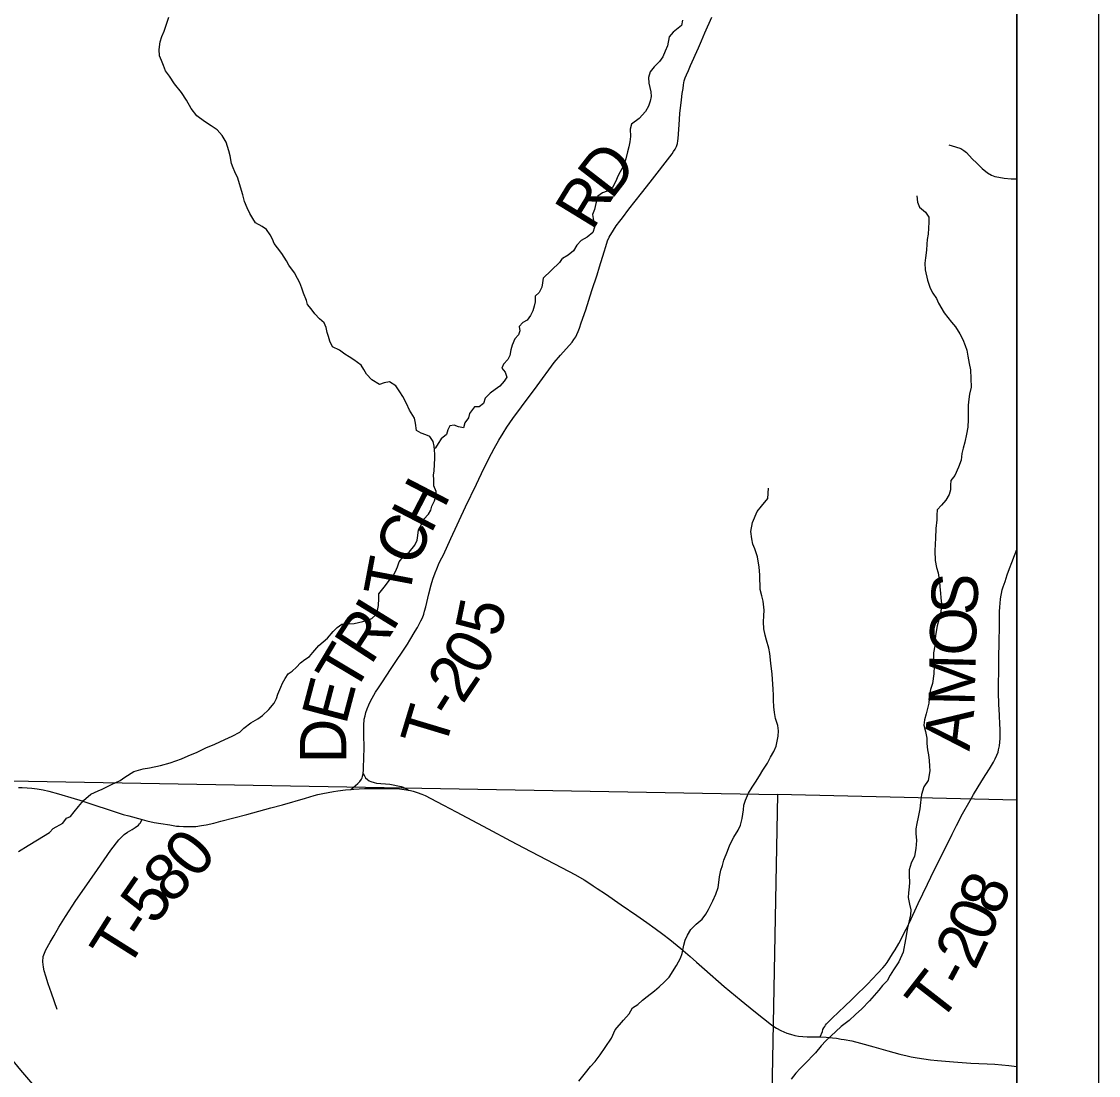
# Model space of a CAD drawing. Extents: x 0 to 34, y 0 to 22.
# Drawn here: x 7.678 to 9, y 16.54 to 17.833 of the extents above; entities that cross this region are included whole.
import ezdxf

# ---------------------------------------------------------------- set-up
doc = ezdxf.new("R2010")
doc.units = 0
for name, color, linetype in [('GM_X_County_Road', 7, 'Continuous'), ('GM_X_Interchange_Ramps', 7, 'Continuous'), ('GM_X_Interstate_Route', 7, 'Continuous'), ('GM_X_Minor_Lake', 7, 'Continuous'), ('GM_X_Section', 7, 'Continuous'), ('GM_X_Township_Road_Text', 7, 'Continuous'), ('GM_X_Unincorporated_Text', 7, 'Continuous'), ('SH_Cut_Line', 7, 'Continuous'), ('SH_Data', 7, 'Continuous')]:
    doc.layers.add(name, color=color, linetype=linetype)

msp = doc.modelspace()

# ---------------------------------------------------------------- linework, layer by layer
at = {"layer": 'GM_X_County_Road'}
msp.add_lwpolyline([(8.9, 16.3458), (8.8896, 16.3484), (8.8415, 16.3566), (8.7835, 16.3626), (8.6949, 16.3631), (8.0785, 16.3449), (8.0171, 16.3505), (7.9686, 16.3596), (7.9232, 16.3737), (7.8664, 16.3974), (7.8219, 16.4192), (7.7822, 16.4429), (7.7542, 16.4676), (7.7187, 16.4982), (7.6774, 16.5465), (7.4755, 16.7917), (7.4147, 16.863), (7.366, 16.9092), (7.315, 16.9447), (7.2325, 16.9942), (7.0394, 17.1127), (6.8369, 17.2379), (6.5407, 17.4237)], dxfattribs=at)
at = {"layer": 'GM_X_Interchange_Ramps'}
msp.add_lwpolyline([(6.5113, 14.1), (8.9, 14.1), (8.9, 17.8921), (8.5492, 17.9006), (8.3297, 17.9059), (7.6027, 17.9156), (6.5943, 17.9356), (6.5883, 17.471), (6.5647, 16.5359), (6.5572, 16.1864), (6.5411, 15.4243), (6.5389, 15.3228)], close=True, dxfattribs=at)
for points in [[(7.6744, 16.8931), (7.6789, 16.8932), (7.6851, 16.893), (7.6909, 16.8924), (7.6973, 16.8916), (7.7048, 16.8902), (7.7118, 16.8886), (7.7235, 16.8855), (7.7428, 16.8798), (7.7498, 16.8776), (7.8031, 16.8603), (7.81, 16.8583), (7.8264, 16.8538), (7.8321, 16.8525), (7.841, 16.8504), (7.8492, 16.8489), (7.8601, 16.8473), (7.8684, 16.846), (7.8716, 16.8457), (7.8772, 16.8455), (7.8847, 16.8454), (7.8921, 16.8456), (7.8991, 16.8465), (7.9049, 16.8474), (7.9141, 16.8495), (7.9229, 16.8518), (7.9546, 16.86), (7.9841, 16.8683), (7.9987, 16.8721), (8.0268, 16.8802), (8.0373, 16.8833), (8.0421, 16.8845), (8.0479, 16.8859), (8.0613, 16.8885), (8.0666, 16.8893), (8.0757, 16.8903), (8.0825, 16.8909), (8.0862, 16.8913), (8.0992, 16.8919), (8.1214, 16.8922), (8.1349, 16.892), (8.1421, 16.8916), (8.1478, 16.8909), (8.1531, 16.8901)], [(8.1531, 16.8901), (8.1555, 16.8897), (8.1591, 16.8888), (8.1639, 16.8873), (8.1695, 16.8852), (8.1737, 16.8833), (8.1877, 16.8762), (8.1963, 16.8717), (8.2118, 16.8636), (8.2511, 16.8425), (8.2784, 16.8279), (8.2949, 16.8194), (8.3409, 16.7951), (8.3581, 16.786), (8.3686, 16.7799), (8.3759, 16.7753), (8.3798, 16.7728), (8.3849, 16.7694), (8.3951, 16.7627), (8.4142, 16.7495), (8.4333, 16.7363), (8.4457, 16.7275), (8.456, 16.7202), (8.4655, 16.7132), (8.4739, 16.7067), (8.4875, 16.6956), (8.4989, 16.6858), (8.5066, 16.6788), (8.5163, 16.6703), (8.5406, 16.6493), (8.5616, 16.632), (8.5771, 16.6191), (8.5888, 16.6097), (8.5945, 16.6053), (8.5993, 16.6017), (8.605, 16.5981), (8.6102, 16.5951), (8.6138, 16.5934), (8.6177, 16.5919), (8.6222, 16.5905), (8.6273, 16.5892), (8.6318, 16.5884), (8.6372, 16.5878), (8.6425, 16.5875), (8.6486, 16.5873), (8.6583, 16.5874)], [(8.6583, 16.5874), (8.666, 16.5871), (8.6734, 16.5863), (8.6784, 16.5857), (8.6843, 16.5847), (8.6877, 16.584), (8.6971, 16.5823), (8.7078, 16.5796), (8.7244, 16.5752), (8.733, 16.5727), (8.7415, 16.5704), (8.7562, 16.5662), (8.7651, 16.5641), (8.7702, 16.563), (8.7775, 16.5617), (8.7855, 16.5604), (8.794, 16.5593), (8.8024, 16.5582), (8.8121, 16.5574), (8.8222, 16.5566), (8.8433, 16.5552), (8.8532, 16.5546), (8.8636, 16.5544), (8.8727, 16.554), (8.8814, 16.5532), (8.8901, 16.5524), (8.9, 16.551)]]:
    msp.add_lwpolyline(points, dxfattribs=at)
at = {"layer": 'GM_X_Interstate_Route'}
for points in [[(8.0825, 16.8909), (8.0854, 16.8932), (8.0883, 16.8957), (8.091, 16.8982), (8.0933, 16.9005), (8.0955, 16.9033), (8.0963, 16.9051), (8.0969, 16.9069), (8.0977, 16.9103), (8.0979, 16.9148), (8.0981, 16.9178), (8.0985, 16.9292), (8.0988, 16.9423), (8.0984, 16.958), (8.0983, 16.9669), (8.0985, 16.9717), (8.0986, 16.9745), (8.0989, 16.9769), (8.0998, 16.981), (8.1009, 16.9852), (8.1026, 16.9896), (8.1044, 16.9946), (8.1064, 16.999), (8.1127, 17.0101), (8.1163, 17.0157), (8.1203, 17.0218), (8.1318, 17.0391), (8.1518, 17.0692), (8.1547, 17.0738), (8.1613, 17.0849), (8.1642, 17.0895), (8.1684, 17.0978), (8.1702, 17.1012), (8.1719, 17.1059), (8.173, 17.1096), (8.1745, 17.115), (8.1782, 17.1306), (8.1811, 17.1417), (8.1831, 17.1487), (8.1859, 17.1564), (8.1879, 17.1614), (8.191, 17.1687), (8.1941, 17.175), (8.196, 17.1788), (8.2053, 17.1987), (8.2233, 17.2376), (8.2365, 17.2654), (8.2458, 17.2847), (8.255, 17.3029), (8.2582, 17.3089), (8.264, 17.3193), (8.2692, 17.3279), (8.2738, 17.3351), (8.2814, 17.3457), (8.2917, 17.36), (8.3109, 17.3859), (8.3321, 17.4146), (8.3399, 17.4237), (8.3542, 17.4396), (8.3563, 17.4427), (8.3584, 17.4462), (8.3599, 17.4491), (8.3614, 17.4527), (8.363, 17.4566), (8.3652, 17.4633), (8.3707, 17.4791), (8.3782, 17.5027), (8.3846, 17.5222), (8.3878, 17.5318), (8.3935, 17.5504), (8.3954, 17.557), (8.3974, 17.5637), (8.3994, 17.5681), (8.4047, 17.577), (8.4082, 17.5821), (8.4127, 17.5881), (8.4158, 17.592), (8.4238, 17.6026), (8.4392, 17.6222), (8.4496, 17.6358), (8.4766, 17.6704), (8.4786, 17.6733), (8.4805, 17.6764), (8.4822, 17.6797), (8.4832, 17.6832), (8.4837, 17.6863), (8.4841, 17.6893), (8.4853, 17.7059), (8.4864, 17.7198), (8.4883, 17.7368), (8.489, 17.7446), (8.4901, 17.7507), (8.4907, 17.7551), (8.4916, 17.76), (8.4929, 17.7636), (8.4945, 17.7673), (8.4968, 17.7729), (8.4993, 17.7788), (8.5093, 17.8007), (8.5128, 17.809), (8.517, 17.8189), (8.5254, 17.8382)], [(8.8163, 17.6816), (8.8247, 17.6792), (8.8309, 17.6771), (8.8349, 17.6747), (8.838, 17.672), (8.8448, 17.6643), (8.8507, 17.6589), (8.8573, 17.6527), (8.8637, 17.6473), (8.8687, 17.6445), (8.8727, 17.6429), (8.8776, 17.6417), (8.8841, 17.6407), (8.893, 17.64), (8.9, 17.64)], [(8.6583, 16.5874), (8.6611, 16.5941), (8.6619, 16.5962), (8.6629, 16.5983), (8.664, 16.6001), (8.6649, 16.6016), (8.6663, 16.6034), (8.6689, 16.6061), (8.6732, 16.6103), (8.6887, 16.6249), (8.6969, 16.6328), (8.7007, 16.6364), (8.7165, 16.6519), (8.7289, 16.6651), (8.7353, 16.672), (8.7384, 16.6754), (8.7407, 16.6787), (8.7441, 16.6838), (8.7474, 16.6893), (8.7504, 16.6943), (8.7548, 16.7019), (8.7639, 16.7196), (8.7679, 16.7277), (8.7789, 16.7508), (8.7901, 16.7745), (8.7944, 16.7831), (8.803, 16.8009), (8.8068, 16.8087), (8.8203, 16.8359), (8.8256, 16.8466), (8.8333, 16.8608), (8.8425, 16.8772), (8.8468, 16.8846), (8.8568, 16.9013), (8.8616, 16.909), (8.8663, 16.9163), (8.8711, 16.9242), (8.8734, 16.9285), (8.8754, 16.9329), (8.8767, 16.9364), (8.8775, 16.9393), (8.8784, 16.9443), (8.8789, 16.949), (8.8792, 16.9533), (8.8794, 16.9657), (8.8791, 16.9701), (8.8784, 16.9822), (8.8779, 16.9949), (8.8774, 17.01), (8.8773, 17.0175), (8.8776, 17.0389), (8.8778, 17.051), (8.8781, 17.0727), (8.8784, 17.09), (8.8787, 17.109), (8.879, 17.1145), (8.8798, 17.1241), (8.8801, 17.127), (8.8809, 17.1313), (8.882, 17.1356), (8.8832, 17.1394), (8.8853, 17.1458), (8.888, 17.154), (8.8908, 17.1618), (8.8936, 17.1693), (8.897, 17.1777), (8.9, 17.185)], [(8.0977, 16.9103), (8.099, 16.9076), (8.1004, 16.9053), (8.1027, 16.9031), (8.105, 16.9016), (8.1069, 16.9006), (8.1111, 16.8993), (8.1139, 16.8986), (8.1302, 16.8973), (8.1324, 16.8969), (8.142, 16.895), (8.1442, 16.8943), (8.1466, 16.8935), (8.1494, 16.8922), (8.151, 16.8914), (8.1531, 16.8901)], [(7.7221, 16.6209), (7.7149, 16.6408), (7.7109, 16.6524), (7.7079, 16.6619), (7.7062, 16.6682), (7.705, 16.6727), (7.7046, 16.676), (7.7043, 16.6796), (7.7049, 16.6858), (7.7064, 16.69), (7.7082, 16.6943), (7.7134, 16.7037), (7.7182, 16.7119), (7.7241, 16.7221), (7.7323, 16.7349), (7.7449, 16.7545), (7.7525, 16.7657), (7.7619, 16.7792), (7.7716, 16.7925), (7.7877, 16.8163), (7.7977, 16.8292), (7.8012, 16.8328), (7.8044, 16.8357), (7.8085, 16.8385), (7.8139, 16.8417), (7.8179, 16.8441), (7.8217, 16.8471), (7.8231, 16.8486), (7.8239, 16.8496), (7.8264, 16.8538)]]:
    msp.add_lwpolyline(points, dxfattribs=at)
at = {"layer": 'GM_X_Minor_Lake'}
msp.add_lwpolyline([(7.5942, 16.9027), (8.606, 16.8847), (8.5869, 15.8686), (7.5725, 15.8874)], close=True, dxfattribs=at)
at = {"layer": 'GM_X_Township_Road_Text'}
for points in [[(7.9788, 17.5777), (7.9735, 17.5814), (7.9654, 17.5859), (7.962, 17.5912), (7.9585, 17.5972), (7.9553, 17.6044), (7.9518, 17.612), (7.9498, 17.6203), (7.947, 17.6298), (7.9438, 17.6408), (7.94, 17.6483), (7.938, 17.6533), (7.936, 17.6586), (7.9344, 17.6681), (7.9328, 17.6741), (7.9292, 17.6848), (7.9246, 17.6931), (7.9184, 17.6998), (7.9108, 17.7047), (7.9027, 17.7102), (7.8935, 17.7173), (7.8866, 17.726), (7.8808, 17.7362), (7.8746, 17.7456), (7.8661, 17.7565), (7.8599, 17.7656), (7.8549, 17.7724), (7.8525, 17.7788), (7.8502, 17.7849), (7.8475, 17.7909), (7.847, 17.7985), (7.8484, 17.8077), (7.8505, 17.8146), (7.8535, 17.8211), (7.8564, 17.8307), (7.8589, 17.838)], [(8.4896, 17.8345), (8.4881, 17.828), (8.4782, 17.8197), (8.4732, 17.814), (8.4709, 17.803), (8.4682, 17.7965), (8.4655, 17.7897), (8.4613, 17.7836), (8.4545, 17.7772), (8.4499, 17.7711), (8.4476, 17.7642), (8.4483, 17.7574), (8.4505, 17.7467), (8.4509, 17.7407), (8.4497, 17.735), (8.4478, 17.7289), (8.4439, 17.7224), (8.4363, 17.7137), (8.4268, 17.7069), (8.4253, 17.7008), (8.4256, 17.6917), (8.4248, 17.6852), (8.4236, 17.6791), (8.4221, 17.6731), (8.4198, 17.6643), (8.4175, 17.6567), (8.4106, 17.6438), (8.4071, 17.6362), (8.4037, 17.6294), (8.3972, 17.6249), (8.3911, 17.6226), (8.3854, 17.6184), (8.3831, 17.6097), (8.3815, 17.6021), (8.3792, 17.596), (8.3807, 17.5861), (8.3814, 17.5804), (8.3795, 17.574), (8.3723, 17.5683), (8.365, 17.5641), (8.3597, 17.5584), (8.3555, 17.5516), (8.349, 17.5463), (8.3422, 17.5421), (8.342, 17.5419)], [(8.777, 17.6189), (8.7781, 17.6113), (8.7803, 17.6052), (8.7879, 17.5991), (8.792, 17.593), (8.792, 17.5865), (8.7908, 17.5721), (8.7896, 17.5656), (8.7892, 17.5599), (8.7888, 17.5523), (8.7876, 17.5428), (8.7868, 17.5364), (8.7872, 17.5284), (8.7902, 17.5154), (8.7935, 17.5059), (8.7969, 17.4998), (8.8011, 17.493), (8.8037, 17.4872), (8.8108, 17.4754), (8.8195, 17.464), (8.8244, 17.4583), (8.8297, 17.4499), (8.8335, 17.4427), (8.8365, 17.4354), (8.8383, 17.4297), (8.8398, 17.4225), (8.8413, 17.4133), (8.8428, 17.4057), (8.8435, 17.3951), (8.8438, 17.3844), (8.8419, 17.3757), (8.8407, 17.3696), (8.8399, 17.3624), (8.8399, 17.3533), (8.8402, 17.3445), (8.8398, 17.3354), (8.8382, 17.3267), (8.8359, 17.3168), (8.834, 17.3096), (8.8324, 17.3031), (8.8313, 17.2948), (8.8282, 17.286), (8.8236, 17.2758), (8.819, 17.2697), (8.8186, 17.264), (8.8186, 17.2583), (8.8167, 17.2526), (8.8125, 17.2458), (8.8075, 17.2397), (8.8022, 17.234), (8.8017, 17.2272), (8.8017, 17.2215), (8.8005, 17.2109), (8.8001, 17.1991), (8.7997, 17.1919), (8.7993, 17.1835), (8.7996, 17.1717), (8.8011, 17.1633), (8.8033, 17.1565), (8.8048, 17.1455), (8.8055, 17.1394), (8.8062, 17.1318), (8.8066, 17.1257), (8.8073, 17.1185), (8.8065, 17.1082), (8.8042, 17.0991), (8.8019, 17.0915), (8.8003, 17.082), (8.7995, 17.0759), (8.7991, 17.0672), (8.7976, 17.0584), (8.7975, 17.0527), (8.7983, 17.0425), (8.7978, 17.0326), (8.7963, 17.0208), (8.794, 17.0136), (8.7928, 17.0068), (8.792, 16.9965), (8.7885, 16.9836), (8.7866, 16.9764), (8.7858, 16.9699), (8.7877, 16.9619), (8.7895, 16.9536), (8.7895, 16.9471), (8.7902, 16.9395), (8.7913, 16.9334), (8.7924, 16.9262), (8.7928, 16.9193), (8.7931, 16.9136), (8.7908, 16.9019), (8.7855, 16.8939), (8.7828, 16.8848), (8.7816, 16.8749), (8.7808, 16.8669), (8.7788, 16.857), (8.7769, 16.8491), (8.7757, 16.8426), (8.7757, 16.8369), (8.7768, 16.8282), (8.776, 16.8183), (8.7741, 16.8092)], [(7.9912, 17.0025), (7.993, 17.0079), (7.9963, 17.0163), (7.9985, 17.0213), (8.0018, 17.0271), (8.0055, 17.0328), (8.0104, 17.0359), (8.0156, 17.041), (8.0205, 17.046), (8.0261, 17.0503), (8.0317, 17.0538), (8.0358, 17.0588), (8.0433, 17.0673), (8.0538, 17.0766), (8.0608, 17.0847), (8.0657, 17.0897), (8.0713, 17.0936), (8.0766, 17.0941), (8.0864, 17.0946), (8.097, 17.0967), (8.103, 17.0983), (8.1083, 17.1006), (8.1135, 17.1053), (8.115, 17.1103), (8.1164, 17.1164), (8.1167, 17.1251), (8.1166, 17.1308), (8.1248, 17.1409), (8.1296, 17.147), (8.1344, 17.1528), (8.1374, 17.1582), (8.1396, 17.1639), (8.1418, 17.1701), (8.1462, 17.1758), (8.1541, 17.1821), (8.1608, 17.1905), (8.1637, 17.1967), (8.1648, 17.2024), (8.1654, 17.2093), (8.1695, 17.2166), (8.1721, 17.2223), (8.1776, 17.2285), (8.1806, 17.2335), (8.182, 17.2385), (8.185, 17.245), (8.1868, 17.2507), (8.1871, 17.2564), (8.1843, 17.2632), (8.1842, 17.2712), (8.1838, 17.2762), (8.1845, 17.2815), (8.1854, 17.2971), (8.1853, 17.3021), (8.1848, 17.312), (8.1836, 17.3177), (8.1793, 17.3237), (8.1744, 17.3259), (8.1687, 17.3277), (8.1629, 17.3311), (8.1617, 17.3402), (8.1604, 17.3463), (8.1546, 17.3561), (8.1507, 17.3644), (8.1461, 17.3727), (8.1426, 17.3784), (8.1375, 17.3859), (8.1299, 17.3907), (8.1235, 17.3895), (8.1174, 17.3875), (8.1083, 17.3935), (8.1017, 17.4002), (8.0983, 17.4059), (8.0951, 17.4112), (8.086, 17.4179), (8.0802, 17.4216), (8.0749, 17.4246), (8.0684, 17.4298), (8.06, 17.4338), (8.0565, 17.4406), (8.0549, 17.4463), (8.0533, 17.4513), (8.0521, 17.4573), (8.0497, 17.4634), (8.044, 17.4683), (8.0382, 17.4743), (8.0336, 17.4803), (8.0293, 17.4856), (8.0278, 17.4905), (8.0242, 17.4996), (8.0222, 17.5056), (8.0199, 17.5121), (8.0168, 17.5177), (8.0133, 17.5245), (8.0063, 17.534), (8.0036, 17.5392), (7.9978, 17.5483), (7.9924, 17.5554), (7.9885, 17.5607), (7.9862, 17.566), (7.9834, 17.5713), (7.9788, 17.5777)], [(8.3418, 17.542), (8.3385, 17.5373), (8.3185, 17.5182), (8.3175, 17.5124), (8.3168, 17.5071), (8.3135, 17.5006), (8.3086, 17.4959), (8.3087, 17.4891), (8.3073, 17.4837), (8.3058, 17.478), (8.3029, 17.4722), (8.2988, 17.4664), (8.2936, 17.4637), (8.2891, 17.4587), (8.2899, 17.4534), (8.2881, 17.4484), (8.2836, 17.4434), (8.2803, 17.4357), (8.2789, 17.43), (8.2775, 17.4231), (8.2753, 17.4181), (8.2697, 17.4127), (8.2678, 17.4077), (8.2717, 17.4028), (8.2737, 17.3967), (8.2707, 17.3917), (8.2651, 17.3856), (8.2595, 17.3813), (8.2535, 17.377), (8.2472, 17.3708), (8.2454, 17.3643), (8.2398, 17.36), (8.2341, 17.36), (8.2281, 17.3519), (8.2267, 17.3465), (8.2222, 17.3404), (8.2208, 17.3346), (8.2144, 17.3357), (8.2094, 17.3375), (8.2041, 17.337), (8.2015, 17.332), (8.1997, 17.3263), (8.1934, 17.3209), (8.1897, 17.3151), (8.1863, 17.3097), (8.185, 17.3087)], [(8.3623, 16.5332), (8.3703, 16.5434), (8.3764, 16.551), (8.3821, 16.5571), (8.3883, 16.5654), (8.3944, 16.5745), (8.4024, 16.5859), (8.407, 16.5958), (8.4169, 16.6079), (8.4241, 16.6158), (8.428, 16.623), (8.4348, 16.6272), (8.4405, 16.6325), (8.4462, 16.637), (8.455, 16.6438), (8.4607, 16.6488), (8.4672, 16.6548), (8.4733, 16.6605), (8.4821, 16.6749), (8.487, 16.684), (8.489, 16.6897), (8.4913, 16.7), (8.4928, 16.706), (8.4955, 16.7121), (8.4997, 16.7189), (8.5062, 16.7258), (8.5138, 16.7318), (8.518, 16.7379), (8.5215, 16.7436), (8.5268, 16.7542), (8.5303, 16.7625), (8.5333, 16.7705), (8.5341, 16.7766), (8.5349, 16.7838), (8.5365, 16.7918), (8.5384, 16.7975), (8.5403, 16.8043), (8.5445, 16.8153), (8.5476, 16.8229), (8.5526, 16.8324), (8.5579, 16.8411), (8.5606, 16.8472), (8.5629, 16.8552), (8.5645, 16.8658), (8.5649, 16.8715), (8.5668, 16.8776), (8.5703, 16.8863), (8.5749, 16.8935), (8.5791, 16.8996), (8.584, 16.9075), (8.5882, 16.9144), (8.5936, 16.9231), (8.5974, 16.9303), (8.6016, 16.9375), (8.6043, 16.944), (8.607, 16.9561), (8.6074, 16.9629), (8.6063, 16.9694), (8.6037, 16.9778), (8.6022, 16.9854), (8.6015, 16.9922), (8.6011, 17.0002), (8.6012, 17.0067), (8.6008, 17.0139), (8.6001, 17.0261), (8.5994, 17.0322), (8.5979, 17.0458), (8.5965, 17.0576), (8.5953, 17.0641), (8.5924, 17.074), (8.5909, 17.0801), (8.5894, 17.0877), (8.589, 17.0964), (8.5895, 17.104), (8.5899, 17.1109), (8.5884, 17.1219), (8.5869, 17.1284), (8.585, 17.136), (8.5847, 17.1417), (8.5843, 17.1481), (8.5844, 17.1542), (8.5837, 17.1634), (8.5814, 17.1763), (8.5781, 17.1862), (8.5758, 17.1919), (8.5747, 17.1984), (8.5732, 17.2071), (8.5752, 17.2185), (8.5813, 17.2318), (8.5863, 17.2382), (8.5943, 17.2477), (8.5951, 17.2603)], [(7.6744, 16.8146), (7.6864, 16.822), (7.698, 16.829), (7.7126, 16.838), (7.7171, 16.843), (7.7288, 16.8497), (7.7336, 16.8555), (7.7385, 16.8578), (7.7429, 16.8636), (7.7482, 16.8701), (7.7541, 16.8775), (7.7635, 16.8852), (7.7721, 16.8892), (7.7774, 16.8911), (7.7823, 16.8935), (7.7887, 16.897), (7.7992, 16.9018), (7.8052, 16.906), (7.8161, 16.9127), (7.8274, 16.9163), (7.8353, 16.9172), (7.8489, 16.9204), (7.8606, 16.9236), (7.8745, 16.9284), (7.8828, 16.932), (7.8937, 16.9367), (7.9046, 16.9418), (7.9155, 16.9466), (7.9276, 16.9521), (7.9366, 16.9564), (7.946, 16.9611), (7.9512, 16.9661), (7.9595, 16.9727), (7.9681, 16.9774), (7.9741, 16.9817), (7.9816, 16.9891), (7.9883, 16.9968), (7.9912, 17.0025)], [(8.7741, 16.8092), (8.7702, 16.8004), (8.7675, 16.7921), (8.7675, 16.7853), (8.7682, 16.7769), (8.7678, 16.7712), (8.7667, 16.764), (8.7663, 16.7583), (8.7681, 16.7503), (8.7696, 16.7431), (8.7692, 16.737), (8.7677, 16.7298), (8.7657, 16.721), (8.763, 16.707), (8.7603, 16.6914), (8.7549, 16.6796), (8.7484, 16.6694), (8.7442, 16.663), (8.7408, 16.6561), (8.7351, 16.6504), (8.7305, 16.6448), (8.719, 16.6315), (8.7095, 16.6217), (8.7019, 16.6148), (8.6939, 16.6073), (8.6844, 16.6001), (8.6714, 16.5883), (8.6653, 16.5827), (8.6596, 16.5762), (8.6527, 16.5679), (8.6394, 16.5539), (8.6337, 16.5486), (8.6287, 16.5429), (8.623, 16.5353)]]:
    msp.add_lwpolyline(points, dxfattribs=at)
at = {"layer": 'GM_X_Unincorporated_Text'}
msp.add_lwpolyline([(8.9, 15.8651), (8.9, 16.8779), (8.606, 16.8847), (8.5869, 15.8686)], close=True, dxfattribs=at)
at = {"layer": 'SH_Cut_Line'}
msp.add_lwpolyline([(2.1, 17.9098), (2.1, 14.1), (8.9, 14.1), (8.9, 17.8921), (8.5492, 17.9006), (8.3297, 17.9059), (7.6027, 17.9156), (6.5943, 17.9356), (6.24, 17.9427), (6.0729, 17.9463), (5.6339, 17.9555), (5.3871, 17.9608), (4.994, 17.969), (4.9368, 17.9702), (4.9267, 17.9702), (4.5919, 17.9719), (4.4481, 17.9728), (4.1825, 17.9744), (3.7128, 17.9822), (3.7063, 17.8588), (3.604, 17.8577), (2.9484, 17.8857), (2.6711, 17.8975), (2.4376, 17.9025)], close=True, dxfattribs=at)
at = {"layer": 'SH_Data'}
for p, q in [((9, 21), (9, 14)), ((8.9, 20.9), (8.9, 14.1))]:
    msp.add_line(p, q, dxfattribs=at)

# ---------------------------------------------------------------- texts
at = {"layer": 'GM_X_Section'}
for s, rotation, p in [('D', 52.3017, (8.4021, 17.613)), ('R', 58.5556, (8.3787, 17.5746)), ('H', 62.5633, (8.1805, 17.2031)), ('C', 64.0371, (8.1602, 17.1615)), ('T', 79.3161, (8.1536, 17.1235)), ('S', 87.148, (8.8507, 17.1041)), ('I', 58.4119, (8.1332, 17.0826)), ('5', 78.6219, (8.2655, 17.0764)), ('R', 56.9702, (8.107, 17.0422)), ('O', 88.4298, (8.8493, 17.0544)), ('0', 61.0799, (8.2421, 17.028)), ('T', 59.2185, (8.0855, 17.0062)), ('2', 56.0718, (8.2197, 16.9943)), ('M', 88.7467, (8.848, 16.9929)), ('E', 75.2185, (8.0763, 16.9689)), ('-', 57.8862, (8.2076, 16.975)), ('T', 73.2187, (8.197, 16.9379)), ('A', 83.2744, (8.8417, 16.9373)), ('D', 89.8907, (8.0767, 16.9227)), ('0', 50.5639, (7.8928, 16.779)), ('8', 41.9002, (7.8603, 16.7489)), ('8', 67.251, (8.8781, 16.7342)), ('5', 55.2245, (7.8426, 16.7227)), ('0', 66.9439, (8.8643, 16.7017)), ('T', 57.7852, (7.8076, 16.6678)), ('-', 56.8122, (7.8301, 16.7035)), ('2', 64.8266, (8.8485, 16.6679)), ('T', 52.1246, (8.8042, 16.6021)), ('-', 61.8775, (8.836, 16.6445))]:
    msp.add_text(s, height=0.0568, rotation=rotation, dxfattribs=at).set_placement(p)

doc.saveas('drawing.dxf')
